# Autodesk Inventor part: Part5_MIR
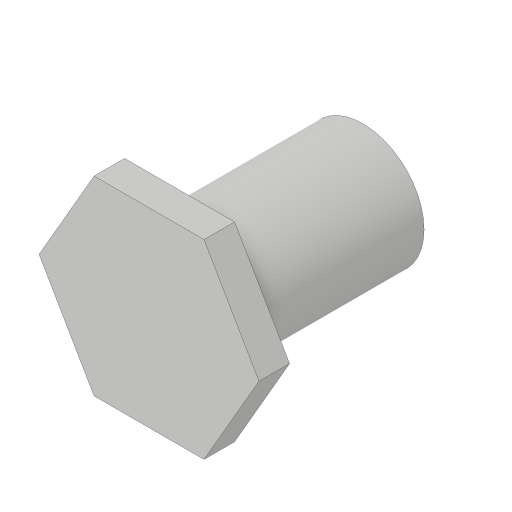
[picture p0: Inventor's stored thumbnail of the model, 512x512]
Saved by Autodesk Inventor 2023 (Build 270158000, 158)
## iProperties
Created: 2008-05
Part Number: Part5_MIR
Material: Generic
Document SubType Name: Modeling
Designer: CADCIM 00
Density: 1 g/cm^3
Appearance: Default
Author: CADCIM
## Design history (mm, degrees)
derived "Part5.ipt"
  sketch "Sketch1"
    geometry: C1 r 2 at (7.12, 11.618) reference
  sketch "Sketch2"
    geometry: L1 (3.598, 0)-(1.799, 3.116) reference; L2 (1.799, 3.116)-(-1.799, 3.116) reference; L3 (-1.799, 3.116)-(-3.598, 0) reference; L4 (-3.598, 0)-(-1.799, -3.116) reference; L5 (-1.799, -3.116)-(1.799, -3.116) reference; L6 (1.799, -3.116)-(3.598, 0) reference; C1 r 2 at (0, 0) reference; 1 further point
    constraints: 1 other
feature "Solid1::Part5.ipt" dims "d0" = 10
tag "TaggingFeature1"
body "Solid1"
